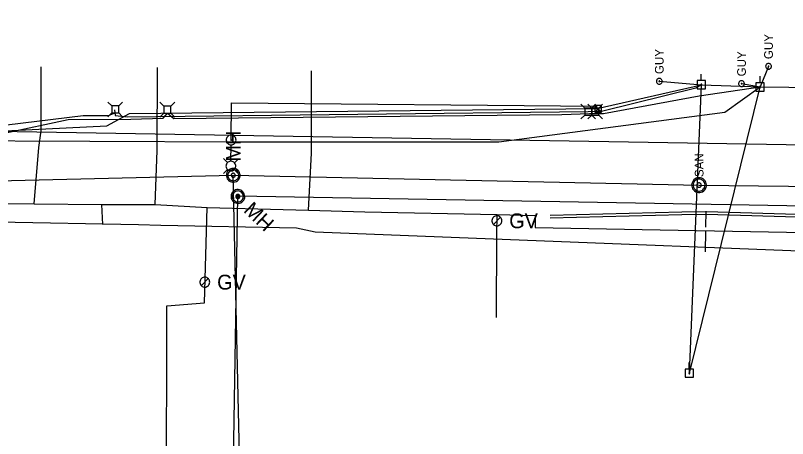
# Model space of a CAD drawing. Extents: x 596028 to 606371, y 330010 to 403088.
# Drawn here: x 603798.7 to 604142, y 337908.1 to 338096 of the extents above; entities that cross this region are included whole.
import ezdxf

# ---------------------------------------------------------------- set-up
doc = ezdxf.new("R2010")
doc.units = 0
for name, color, linetype in [('E_LTG', 7, 'Continuous'), ('E_LTG_CID', 7, 'Continuous'), ('E_UTL_AG_Bold', 7, 'Continuous'), ('E_UTL_E_UG', 7, 'Continuous'), ('E_UTL_EGuyWire', 7, 'Continuous'), ('E_UTL_EPowerPole', 7, 'Continuous'), ('E_UTL_ETransformer', 7, 'Continuous'), ('E_UTL_G', 7, 'Continuous'), ('E_UTL_G_UG', 7, 'Continuous'), ('E_UTL_Overhead', 7, 'Continuous'), ('E_UTL_SAN', 7, 'Continuous'), ('E_UTL_SAN_MH', 7, 'Continuous'), ('E_UTL_SAN_UG', 7, 'Continuous'), ('E_UTL_SAN_UG_MMSD', 7, 'Continuous'), ('E_UTL_T', 7, 'Continuous'), ('E_UTL_T_UG', 7, 'Continuous'), ('E_UTL_TV_UG', 7, 'Continuous')]:
    doc.layers.add(name, color=color, linetype=linetype)

# ---------------------------------------------------------------- blocks, each defined once
blk = doc.blocks.new('ACAD_PROXY_ENTITY_7')
at = {"layer": 'E_UTL_EPowerPole'}
for points in [[(1841391.1, 1030427.5), (1841391.1, 1030436.4)], [(1841396.7, 1030427.5), (1841385.5, 1030427.5)], [(1841385.5, 1030427.5), (1841385.5, 1030416.3)], [(1841391.9, 1030421.9), (1841391.9, 1030422.1), (1841391.9, 1030422.2), (1841391.8, 1030422.3), (1841391.7, 1030422.4), (1841391.6, 1030422.5), (1841391.5, 1030422.6), (1841391.4, 1030422.6), (1841391.2, 1030422.6), (1841391.1, 1030422.6), (1841391, 1030422.6), (1841390.8, 1030422.5), (1841390.7, 1030422.5), (1841390.6, 1030422.4), (1841390.6, 1030422.2), (1841390.5, 1030422.1), (1841390.5, 1030422), (1841390.5, 1030421.8), (1841390.5, 1030421.7), (1841390.6, 1030421.6), (1841390.6, 1030421.5), (1841390.7, 1030421.4), (1841390.8, 1030421.3), (1841391, 1030421.2), (1841391.1, 1030421.2), (1841391.2, 1030421.2), (1841391.4, 1030421.2), (1841391.5, 1030421.3), (1841391.6, 1030421.3), (1841391.7, 1030421.4), (1841391.8, 1030421.5), (1841391.9, 1030421.6), (1841391.9, 1030421.8), (1841391.9, 1030421.9)], [(1841396.7, 1030416.3), (1841396.7, 1030427.5)], [(1841385.5, 1030416.3), (1841396.7, 1030416.3)]]:
    blk.add_lwpolyline(points, dxfattribs=at)
blk = doc.blocks.new('ACAD_PROXY_ENTITY_8')
at = {"layer": 'E_UTL_AG_Bold'}
for points in [[(1843387.7, 1030160.5), (1843382.4, 1030165.8)], [(1843397.2, 1030160.5), (1843387.7, 1030160.5)], [(1843387.7, 1030160.5), (1843387.7, 1030151)], [(1843397.2, 1030160.5), (1843402.5, 1030165.8)], [(1843397.2, 1030151), (1843397.2, 1030160.5)], [(1843387.7, 1030151), (1843382.4, 1030145.7)], [(1843387.7, 1030151), (1843397.2, 1030151)], [(1843397.2, 1030151), (1843402.5, 1030145.7)]]:
    blk.add_lwpolyline(points, dxfattribs=at)
blk = doc.blocks.new('ACAD_PROXY_ENTITY_10')
at = {"layer": 'E_LTG'}
for points in [[(1842242.7, 1034577.4), (1842242.6, 1034578.7), (1842242.2, 1034579.9), (1842241.6, 1034581), (1842240.9, 1034582), (1842239.9, 1034582.9), (1842238.8, 1034583.5), (1842237.6, 1034583.9), (1842236.4, 1034584.1), (1842235.1, 1034584), (1842233.9, 1034583.7), (1842232.7, 1034583.2), (1842231.7, 1034582.5), (1842230.8, 1034581.5), (1842230.2, 1034580.5), (1842229.7, 1034579.3), (1842229.5, 1034578.1), (1842229.5, 1034576.8), (1842229.7, 1034575.6), (1842230.2, 1034574.4), (1842230.8, 1034573.3), (1842231.7, 1034572.4), (1842232.7, 1034571.7), (1842233.9, 1034571.2), (1842235.1, 1034570.9), (1842236.4, 1034570.8), (1842237.6, 1034571), (1842238.8, 1034571.4), (1842239.9, 1034572), (1842240.9, 1034572.9), (1842241.6, 1034573.9), (1842242.2, 1034575), (1842242.6, 1034576.2), (1842242.7, 1034577.4)], [(1842266.8, 1034582.1), (1842261.4, 1034587.5)], [(1842278.1, 1034577.4), (1842277.9, 1034578.7), (1842277.6, 1034579.9), (1842277, 1034581), (1842276.2, 1034582), (1842275.3, 1034582.9), (1842274.2, 1034583.5), (1842273, 1034583.9), (1842271.7, 1034584.1), (1842270.5, 1034584), (1842269.3, 1034583.7), (1842268.1, 1034583.2), (1842267.1, 1034582.5), (1842266.2, 1034581.5), (1842265.5, 1034580.5), (1842265.1, 1034579.3), (1842264.8, 1034578.1), (1842264.8, 1034576.8), (1842265.1, 1034575.6), (1842265.5, 1034574.4), (1842266.2, 1034573.3), (1842267.1, 1034572.4), (1842268.1, 1034571.7), (1842269.3, 1034571.2), (1842270.5, 1034570.9), (1842271.7, 1034570.8), (1842273, 1034571), (1842274.2, 1034571.4), (1842275.3, 1034572), (1842276.2, 1034572.9), (1842277, 1034573.9), (1842277.6, 1034575), (1842277.9, 1034576.2), (1842278.1, 1034577.4)], [(1842276.1, 1034582.1), (1842281.5, 1034587.5)], [(1842236.6, 1034577.4), (1842236.6, 1034577.5), (1842236.5, 1034577.6), (1842236.5, 1034577.7), (1842236.4, 1034577.8), (1842236.4, 1034577.9), (1842236.3, 1034577.9), (1842236.2, 1034577.9), (1842236.1, 1034578), (1842236, 1034578), (1842235.9, 1034577.9), (1842235.8, 1034577.9), (1842235.7, 1034577.8), (1842235.7, 1034577.8), (1842235.6, 1034577.7), (1842235.6, 1034577.6), (1842235.6, 1034577.5), (1842235.6, 1034577.4), (1842235.6, 1034577.3), (1842235.6, 1034577.2), (1842235.7, 1034577.1), (1842235.7, 1034577.1), (1842235.8, 1034577), (1842235.9, 1034577), (1842236, 1034576.9), (1842236.1, 1034576.9), (1842236.2, 1034577), (1842236.3, 1034577), (1842236.4, 1034577), (1842236.4, 1034577.1), (1842236.5, 1034577.2), (1842236.5, 1034577.3), (1842236.6, 1034577.4), (1842236.6, 1034577.4)], [(1842264.7, 1034577.5), (1842242.8, 1034577.5)], [(1842266.8, 1034572.8), (1842261.4, 1034567.4)], [(1842276.1, 1034572.8), (1842281.5, 1034567.4)]]:
    blk.add_lwpolyline(points, dxfattribs=at)
blk = doc.blocks.new('ACAD_PROXY_ENTITY_11')
at = {"layer": 'E_UTL_SAN'}
for points in [[(1841308.5, 1030298.2), (1841306.7, 1030298.1), (1841305, 1030297.6), (1841303.5, 1030296.8), (1841302.1, 1030295.7), (1841300.9, 1030294.3), (1841300, 1030292.8), (1841299.5, 1030291.1), (1841299.2, 1030289.4), (1841299.3, 1030287.6), (1841299.7, 1030285.9), (1841300.4, 1030284.3), (1841301.5, 1030282.8), (1841302.7, 1030281.6), (1841304.2, 1030280.6), (1841305.9, 1030280), (1841307.6, 1030279.7), (1841309.4, 1030279.7), (1841311.1, 1030280), (1841312.8, 1030280.6), (1841314.3, 1030281.6), (1841315.5, 1030282.8), (1841316.6, 1030284.3), (1841317.3, 1030285.9), (1841317.7, 1030287.6), (1841317.8, 1030289.4), (1841317.6, 1030291.1), (1841317, 1030292.8), (1841316.1, 1030294.3), (1841314.9, 1030295.7), (1841313.5, 1030296.8), (1841312, 1030297.6), (1841310.3, 1030298.1), (1841308.5, 1030298.2)], [(1841308.5, 1030296.4), (1841307.1, 1030296.2), (1841305.7, 1030295.8), (1841304.5, 1030295.2), (1841303.4, 1030294.3), (1841302.4, 1030293.2), (1841301.7, 1030292), (1841301.3, 1030290.7), (1841301.1, 1030289.3), (1841301.1, 1030287.9), (1841301.5, 1030286.5), (1841302.1, 1030285.2), (1841302.9, 1030284), (1841303.9, 1030283.1), (1841305.1, 1030282.3), (1841306.4, 1030281.8), (1841307.8, 1030281.5), (1841309.2, 1030281.5), (1841310.6, 1030281.8), (1841311.9, 1030282.3), (1841313.1, 1030283.1), (1841314.1, 1030284), (1841315, 1030285.2), (1841315.5, 1030286.5), (1841315.9, 1030287.9), (1841315.9, 1030289.3), (1841315.7, 1030290.7), (1841315.3, 1030292), (1841314.6, 1030293.2), (1841313.6, 1030294.3), (1841312.5, 1030295.2), (1841311.3, 1030295.8), (1841309.9, 1030296.2), (1841308.5, 1030296.4)], [(1841308.5, 1030291.7), (1841308, 1030291.7), (1841307.5, 1030291.5), (1841307, 1030291.3), (1841306.6, 1030290.9), (1841306.2, 1030290.5), (1841306, 1030290.1), (1841305.8, 1030289.6), (1841305.7, 1030289.1), (1841305.7, 1030288.5), (1841305.9, 1030288), (1841306.1, 1030287.5), (1841306.4, 1030287.1), (1841306.8, 1030286.7), (1841307.2, 1030286.4), (1841307.7, 1030286.2), (1841308.2, 1030286.1), (1841308.8, 1030286.1), (1841309.3, 1030286.2), (1841309.8, 1030286.4), (1841310.2, 1030286.7), (1841310.6, 1030287.1), (1841310.9, 1030287.5), (1841311.1, 1030288), (1841311.3, 1030288.5), (1841311.3, 1030289.1), (1841311.2, 1030289.6), (1841311, 1030290.1), (1841310.8, 1030290.5), (1841310.4, 1030290.9), (1841310, 1030291.3), (1841309.5, 1030291.5), (1841309, 1030291.7), (1841308.5, 1030291.7)]]:
    blk.add_lwpolyline(points, dxfattribs=at)
blk.add_text('MH', height=20.12, rotation=90, dxfattribs=at).set_placement((1841318.6, 1030307.5))
blk = doc.blocks.new('ACAD_PROXY_ENTITY_19')
at = {"layer": 'E_UTL_G'}
for points in [[(1843225.4, 1030136.5), (1843225.2, 1030137.7), (1843224.9, 1030139), (1843224.3, 1030140.1), (1843223.5, 1030141.1), (1843222.5, 1030141.9), (1843221.4, 1030142.6), (1843220.2, 1030143), (1843219, 1030143.2), (1843217.7, 1030143.1), (1843216.5, 1030142.8), (1843215.3, 1030142.3), (1843214.3, 1030141.5), (1843213.4, 1030140.6), (1843212.7, 1030139.5), (1843212.2, 1030138.4), (1843212, 1030137.1), (1843212, 1030135.8), (1843212.2, 1030134.6), (1843212.7, 1030133.4), (1843213.4, 1030132.3), (1843214.3, 1030131.4), (1843215.3, 1030130.7), (1843216.5, 1030130.1), (1843217.7, 1030129.8), (1843219, 1030129.8), (1843220.2, 1030129.9), (1843221.4, 1030130.4), (1843222.5, 1030131), (1843223.5, 1030131.8), (1843224.3, 1030132.8), (1843224.9, 1030134), (1843225.2, 1030135.2), (1843225.4, 1030136.5)], [(1843213.9, 1030131.7), (1843223.4, 1030141.2)]]:
    blk.add_lwpolyline(points, dxfattribs=at)
blk.add_text('GV', height=20.12, dxfattribs=at).set_placement((1843235.4, 1030126.4))

msp = doc.modelspace()

# ---------------------------------------------------------------- linework, layer by layer
at = {"layer": 'E_LTG_CID'}
msp.add_lwpolyline([(603894.62, 338040.7), (603894.72, 338057.11), (604057.25, 338055.68)], dxfattribs=at)
at = {"layer": 'E_UTL_E_UG'}
msp.add_line((604057.26, 338054.68), (604103.64, 338065.21), dxfattribs=at)
for points in [[(603839.32, 338046.99), (603849.47, 338052.42), (604057.26, 338054.68)], [(603604.81, 338053.24), (603627.15, 338051.8), (603659.4, 338049.36), (603720.29, 338046.02), (603787.9, 338044.47), (603839.32, 338046.99)]]:
    msp.add_lwpolyline(points, dxfattribs=at)
at = {"layer": 'E_UTL_EGuyWire'}
for p, q in [((604133.5, 338073.37), (604129.76, 338064.26)), ((604084.95, 338066.74), (604103.64, 338065.21)), ((604121.49, 338065.7), (604129.76, 338064.26))]:
    msp.add_line(p, q, dxfattribs=at)
for points in [[(604133.5, 338074.66), (604133.26, 338074.63), (604133.02, 338074.56), (604132.81, 338074.45), (604132.61, 338074.3), (604132.45, 338074.12), (604132.33, 338073.91), (604132.25, 338073.67), (604132.22, 338073.43), (604132.23, 338073.19), (604132.29, 338072.95), (604132.39, 338072.73), (604132.53, 338072.53), (604132.71, 338072.36), (604132.91, 338072.23), (604133.14, 338072.14), (604133.38, 338072.09), (604133.62, 338072.09), (604133.86, 338072.14), (604134.09, 338072.23), (604134.29, 338072.36), (604134.47, 338072.53), (604134.61, 338072.73), (604134.71, 338072.95), (604134.77, 338073.19), (604134.78, 338073.43), (604134.75, 338073.67), (604134.67, 338073.91), (604134.54, 338074.12), (604134.38, 338074.3), (604134.19, 338074.45), (604133.98, 338074.56), (604133.74, 338074.63), (604133.5, 338074.66)], [(604133.5, 338073.53), (604133.47, 338073.53), (604133.44, 338073.52), (604133.41, 338073.51), (604133.39, 338073.49), (604133.37, 338073.47), (604133.35, 338073.44), (604133.34, 338073.41), (604133.34, 338073.38), (604133.34, 338073.35), (604133.35, 338073.32), (604133.36, 338073.29), (604133.38, 338073.27), (604133.4, 338073.25), (604133.43, 338073.23), (604133.45, 338073.22), (604133.48, 338073.21), (604133.51, 338073.21), (604133.54, 338073.22), (604133.57, 338073.23), (604133.6, 338073.25), (604133.62, 338073.27), (604133.64, 338073.29), (604133.65, 338073.32), (604133.66, 338073.35), (604133.66, 338073.38), (604133.65, 338073.41), (604133.64, 338073.44), (604133.63, 338073.47), (604133.61, 338073.49), (604133.59, 338073.51), (604133.56, 338073.52), (604133.53, 338073.53), (604133.5, 338073.53)], [(604084.95, 338068.02), (604084.71, 338068), (604084.47, 338067.93), (604084.25, 338067.82), (604084.06, 338067.66), (604083.9, 338067.48), (604083.78, 338067.27), (604083.7, 338067.04), (604083.67, 338066.8), (604083.68, 338066.55), (604083.74, 338066.32), (604083.84, 338066.09), (604083.98, 338065.9), (604084.15, 338065.73), (604084.36, 338065.6), (604084.59, 338065.5), (604084.83, 338065.46), (604085.07, 338065.46), (604085.31, 338065.5), (604085.54, 338065.6), (604085.74, 338065.73), (604085.92, 338065.9), (604086.06, 338066.09), (604086.16, 338066.32), (604086.22, 338066.55), (604086.23, 338066.8), (604086.2, 338067.04), (604086.12, 338067.27), (604085.99, 338067.48), (604085.83, 338067.66), (604085.64, 338067.82), (604085.42, 338067.93), (604085.19, 338068), (604084.95, 338068.02)], [(604084.95, 338066.9), (604084.92, 338066.89), (604084.89, 338066.88), (604084.86, 338066.87), (604084.84, 338066.85), (604084.82, 338066.83), (604084.8, 338066.8), (604084.79, 338066.77), (604084.79, 338066.74), (604084.79, 338066.71), (604084.8, 338066.68), (604084.81, 338066.66), (604084.83, 338066.63), (604084.85, 338066.61), (604084.87, 338066.59), (604084.9, 338066.58), (604084.93, 338066.58), (604084.96, 338066.58), (604084.99, 338066.58), (604085.02, 338066.59), (604085.05, 338066.61), (604085.07, 338066.63), (604085.09, 338066.66), (604085.1, 338066.68), (604085.11, 338066.71), (604085.11, 338066.74), (604085.1, 338066.77), (604085.09, 338066.8), (604085.08, 338066.83), (604085.06, 338066.85), (604085.03, 338066.87), (604085.01, 338066.88), (604084.98, 338066.89), (604084.95, 338066.9)], [(604121.49, 338066.98), (604121.25, 338066.96), (604121.02, 338066.89), (604120.8, 338066.78), (604120.61, 338066.63), (604120.45, 338066.44), (604120.33, 338066.23), (604120.25, 338066), (604120.21, 338065.76), (604120.22, 338065.51), (604120.28, 338065.28), (604120.38, 338065.06), (604120.53, 338064.86), (604120.7, 338064.69), (604120.91, 338064.56), (604121.13, 338064.47), (604121.37, 338064.42), (604121.62, 338064.42), (604121.86, 338064.47), (604122.08, 338064.56), (604122.29, 338064.69), (604122.46, 338064.86), (604122.61, 338065.06), (604122.71, 338065.28), (604122.77, 338065.51), (604122.78, 338065.76), (604122.74, 338066), (604122.66, 338066.23), (604122.54, 338066.44), (604122.38, 338066.63), (604122.19, 338066.78), (604121.97, 338066.89), (604121.74, 338066.96), (604121.49, 338066.98)], [(604121.49, 338065.86), (604121.46, 338065.85), (604121.44, 338065.85), (604121.41, 338065.83), (604121.38, 338065.81), (604121.36, 338065.79), (604121.35, 338065.76), (604121.34, 338065.73), (604121.33, 338065.7), (604121.34, 338065.67), (604121.34, 338065.64), (604121.36, 338065.62), (604121.37, 338065.59), (604121.4, 338065.57), (604121.42, 338065.55), (604121.45, 338065.54), (604121.48, 338065.54), (604121.51, 338065.54), (604121.54, 338065.54), (604121.57, 338065.55), (604121.59, 338065.57), (604121.62, 338065.59), (604121.63, 338065.62), (604121.65, 338065.64), (604121.65, 338065.67), (604121.66, 338065.7), (604121.65, 338065.73), (604121.64, 338065.76), (604121.63, 338065.79), (604121.61, 338065.81), (604121.58, 338065.83), (604121.55, 338065.85), (604121.53, 338065.85), (604121.49, 338065.86)]]:
    msp.add_lwpolyline(points, dxfattribs=at)
at = {"layer": 'E_UTL_EPowerPole'}
for points in [[(604103.61, 338067.05), (604103.61, 338069.96)], [(604129.73, 338066.1), (604129.73, 338069.01)], [(604105.46, 338067.05), (604101.77, 338067.05)], [(604101.77, 338067.05), (604101.77, 338063.36)], [(604103.88, 338065.21), (604103.88, 338065.25), (604103.87, 338065.3), (604103.84, 338065.34), (604103.82, 338065.37), (604103.78, 338065.4), (604103.74, 338065.42), (604103.7, 338065.44), (604103.66, 338065.45), (604103.61, 338065.44), (604103.57, 338065.43), (604103.52, 338065.41), (604103.49, 338065.39), (604103.46, 338065.36), (604103.43, 338065.32), (604103.42, 338065.28), (604103.41, 338065.23), (604103.41, 338065.19), (604103.42, 338065.14), (604103.43, 338065.1), (604103.46, 338065.06), (604103.49, 338065.03), (604103.52, 338065), (604103.57, 338064.98), (604103.61, 338064.97), (604103.66, 338064.97), (604103.7, 338064.98), (604103.74, 338064.99), (604103.78, 338065.01), (604103.82, 338065.04), (604103.84, 338065.08), (604103.87, 338065.12), (604103.88, 338065.16), (604103.88, 338065.21)], [(604105.46, 338063.36), (604105.46, 338067.05)], [(604131.58, 338066.1), (604127.89, 338066.1)], [(604127.89, 338066.1), (604127.89, 338062.41)], [(604130, 338064.26), (604130, 338064.3), (604129.98, 338064.34), (604129.96, 338064.38), (604129.94, 338064.42), (604129.9, 338064.45), (604129.86, 338064.47), (604129.82, 338064.49), (604129.77, 338064.49), (604129.73, 338064.49), (604129.69, 338064.48), (604129.64, 338064.46), (604129.61, 338064.44), (604129.58, 338064.4), (604129.55, 338064.37), (604129.53, 338064.32), (604129.53, 338064.28), (604129.53, 338064.23), (604129.53, 338064.19), (604129.55, 338064.15), (604129.58, 338064.11), (604129.61, 338064.08), (604129.64, 338064.05), (604129.69, 338064.03), (604129.73, 338064.02), (604129.77, 338064.02), (604129.82, 338064.02), (604129.86, 338064.04), (604129.9, 338064.06), (604129.94, 338064.09), (604129.96, 338064.13), (604129.98, 338064.17), (604130, 338064.21), (604130, 338064.26)], [(604131.58, 338062.41), (604131.58, 338066.1)], [(604101.77, 338063.36), (604105.46, 338063.36)], [(604127.89, 338062.41), (604131.58, 338062.41)]]:
    msp.add_lwpolyline(points, dxfattribs=at)
at = {"layer": 'E_UTL_ETransformer'}
for p, q in [((604056.27, 338055.97), (604059.27, 338052.97)), ((604059.27, 338055.97), (604056.27, 338052.97))]:
    msp.add_line(p, q, dxfattribs=at)
msp.add_lwpolyline([(604056.27, 338052.97), (604059.27, 338052.97), (604059.27, 338055.97), (604056.27, 338055.97)], close=True, dxfattribs=at)
at = {"layer": 'E_UTL_G_UG'}
for p, q in [((603810.15, 338044.77), (603810.24, 338073.2)), ((603861.78, 338036.07), (603861.9, 338072.88)), ((603930.29, 338049.48), (603930.36, 338071.45)), ((603860.91, 338012.03), (603861.78, 338036.07)), ((603837.54, 338003.08), (603837.16, 338012.04)), ((604012.66, 337998.63), (604012.83, 338007.59)), ((604012.54, 337961.83), (604012.66, 337998.63))]:
    msp.add_line(p, q, dxfattribs=at)
for points in [[(603929, 338009.55), (603930.35, 338034.75), (603930.29, 338049.48)], [(603807.06, 338012.31), (603809.14, 338037.28), (603810.15, 338044.77)], [(604036.38, 338007.29), (604094.93, 338008.7), (604105.86, 338008.92), (604151.14, 338007.64), (604192.37, 338006.27), (604238.01, 338005.01), (604257.33, 338004.4), (604292.99, 338030.64), (604323.62, 338029.78)], [(604036.41, 338006.09), (604094.96, 338007.5), (604105.86, 338007.72), (604151.1, 338006.44), (604192.34, 338005.07), (604237.98, 338003.81), (604257.71, 338003.19), (604293.37, 338029.43), (604323.59, 338028.58)], [(603659.13, 338014.92), (603660.24, 338014.99), (603710.2, 338013.48), (603807.06, 338012.31), (603837.16, 338012.04), (603860.91, 338012.03), (603883.92, 338010.64)], [(603857.61, 337826.63), (603865.95, 337876.92), (603866.02, 337966.94), (603882.73, 337968.38), (603883.92, 338010.64)], [(603883.92, 338010.64), (603929, 338009.55), (603954.09, 338008.77), (604012.83, 338007.59), (604029.73, 338007.09)], [(604105.59, 338008.98), (604105.5, 338002)], [(604029.73, 338007.09), (604029.74, 338001.83), (604085.34, 338000.71), (604165.59, 337999.27), (604217.37, 337998.29), (604240.59, 337996.82), (604279.37, 337995.16), (604329.48, 337991.52)], [(604105.48, 338000.35), (604105.35, 337991.05)]]:
    msp.add_lwpolyline(points, dxfattribs=at)
at = {"layer": 'E_UTL_Overhead'}
msp.add_line((604098.33, 337937.1), (604103.64, 338065.21), dxfattribs=at)
for points in [[(604103.64, 338065.21), (604129.71, 338064.26), (604269.62, 338062.62), (604344.53, 338119.28), (604560.83, 338082.73), (604641.4, 338068.29), (604696.28, 338059.45), (604715.56, 338054.88), (604786.57, 338054.03), (604829.08, 338053.72), (604872.92, 338052.19), (604977.47, 338050.01), (605123.72, 338048.42), (605215.39, 338038.9)], [(604098.33, 337937.1), (604129.71, 338064.26)]]:
    msp.add_lwpolyline(points, dxfattribs=at)
at = {"layer": 'E_UTL_SAN_MH'}
for points in [[(604102.63, 338023.93), (604102.01, 338023.87), (604101.4, 338023.69), (604100.85, 338023.4), (604100.35, 338023.01), (604099.94, 338022.54), (604099.63, 338022), (604099.42, 338021.4), (604099.33, 338020.78), (604099.36, 338020.16), (604099.51, 338019.55), (604099.77, 338018.98), (604100.14, 338018.46), (604100.59, 338018.03), (604101.12, 338017.69), (604101.7, 338017.46), (604102.32, 338017.34), (604102.94, 338017.34), (604103.56, 338017.46), (604104.14, 338017.69), (604104.67, 338018.03), (604105.12, 338018.46), (604105.49, 338018.98), (604105.75, 338019.55), (604105.9, 338020.16), (604105.93, 338020.78), (604105.84, 338021.4), (604105.63, 338022), (604105.32, 338022.54), (604104.91, 338023.01), (604104.41, 338023.4), (604103.86, 338023.69), (604103.26, 338023.87), (604102.63, 338023.93)], [(604102.63, 338023.27), (604102.13, 338023.22), (604101.65, 338023.08), (604101.2, 338022.85), (604100.81, 338022.54), (604100.48, 338022.16), (604100.23, 338021.72), (604100.07, 338021.25), (604099.99, 338020.75), (604100.02, 338020.25), (604100.14, 338019.76), (604100.34, 338019.31), (604100.64, 338018.9), (604101, 338018.55), (604101.42, 338018.28), (604101.89, 338018.09), (604102.38, 338018), (604102.88, 338018), (604103.37, 338018.09), (604103.84, 338018.28), (604104.26, 338018.55), (604104.63, 338018.9), (604104.92, 338019.31), (604105.13, 338019.76), (604105.24, 338020.25), (604105.27, 338020.75), (604105.2, 338021.25), (604105.03, 338021.72), (604104.78, 338022.16), (604104.45, 338022.54), (604104.06, 338022.85), (604103.61, 338023.08), (604103.13, 338023.22), (604102.63, 338023.27)], [(604102.63, 338021.62), (604102.44, 338021.6), (604102.26, 338021.54), (604102.1, 338021.46), (604101.95, 338021.34), (604101.82, 338021.2), (604101.73, 338021.04), (604101.67, 338020.86), (604101.64, 338020.67), (604101.65, 338020.48), (604101.7, 338020.3), (604101.77, 338020.13), (604101.88, 338019.98), (604102.02, 338019.85), (604102.18, 338019.75), (604102.35, 338019.68), (604102.54, 338019.64), (604102.72, 338019.64), (604102.91, 338019.68), (604103.08, 338019.75), (604103.24, 338019.85), (604103.38, 338019.98), (604103.49, 338020.13), (604103.57, 338020.3), (604103.61, 338020.48), (604103.62, 338020.67), (604103.59, 338020.86), (604103.53, 338021.04), (604103.44, 338021.2), (604103.31, 338021.34), (604103.17, 338021.46), (604103, 338021.54), (604102.82, 338021.6), (604102.63, 338021.62)]]:
    msp.add_lwpolyline(points, dxfattribs=at)
msp.add_circle((603897.65, 338015.63), 0.45, dxfattribs=at)
at = {"layer": 'E_UTL_SAN_UG'}
for p in [(603701.92, 338020.41), (603898.31, 337900.75)]:
    msp.add_line(p, (603895.55, 338024.99), dxfattribs=at)
for points in [[(603895.55, 338024.99), (604102.65, 338020.61)], [(604102.65, 338020.61), (604287.7, 338018.55)]]:
    msp.add_lwpolyline(points, dxfattribs=at)
at = {"layer": 'E_UTL_SAN_UG_MMSD'}
for p, q in [((603141.66, 338055.73), (604202.07, 338037.6)), ((603897.65, 338015.8), (604665.17, 338002.68))]:
    msp.add_line(p, q, dxfattribs=at)
msp.add_lwpolyline([(603886.8, 337355.91), (603897.65, 338015.63)], dxfattribs=at)
at = {"layer": 'E_UTL_T_UG'}
msp.add_line((603599.45, 338007.74), (603853.39, 338003.2), dxfattribs=at)
for points in [[(604053.34, 338053.31), (604059.81, 338053.6), (604101.13, 338063.8), (604103.64, 338065.21)], [(603842.76, 338054.1), (603843.06, 338051.58), (603848.49, 338050.96)], [(603669, 338051.76), (603672.99, 338049.45), (603720.35, 338047.39), (603787.56, 338046.44), (603828.77, 338051.55)], [(603828.77, 338051.55), (603840.09, 338051.61), (603843.08, 338052.7)], [(603848.5, 338050.97), (604053.34, 338053.31)], [(603853.39, 338003.2), (603863.38, 338002.89), (603923.6, 338001.66), (603932.04, 337999.82)], [(603932.04, 337999.82), (604249.26, 337987.48), (604268.59, 337974.93)]]:
    msp.add_lwpolyline(points, dxfattribs=at)
at = {"layer": 'E_UTL_TV_UG'}
for points in [[(603602.69, 338042.21), (603664.91, 338041.66), (603765.11, 338040.43), (603898.32, 338039.89), (604013.63, 338039.78), (604114.06, 338053.03), (604129.71, 338064.26)], [(603604.27, 338051.06), (603665.39, 338048.69), (603667.58, 338052.08), (603673.87, 338048.32), (603727.54, 338041.72), (603760.53, 338043.44), (603794.48, 338043.87), (603822.16, 338049.71), (603850.03, 338049.88), (603864.37, 338050.37), (603866.29, 338052.56), (603869.2, 338050.26), (604041.63, 338052.04), (604053.93, 338052.46), (604060.19, 338052.43), (604102.72, 338060.26), (604129.71, 338064.26)]]:
    msp.add_lwpolyline(points, dxfattribs=at)

# ---------------------------------------------------------------- block references
at = {"layer": 'E_LTG', "xscale": 0.32808333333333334, "yscale": 0.32808333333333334, "rotation": -90.56997623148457}
msp.add_blockref('ACAD_PROXY_ENTITY_10', (270496.32, 945794.27), dxfattribs=at)
at = {"layer": 'E_UTL_EPowerPole', "xscale": 0.32808333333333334, "yscale": 0.32808333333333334}
msp.add_blockref('ACAD_PROXY_ENTITY_7', (-31.44, -127.15), dxfattribs=at)
at = {"layer": 'E_UTL_G', "xscale": 0.32808333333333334, "yscale": 0.32808333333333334}
for p in [(-716.59, 34.16), (-846.42, 6.92)]:
    msp.add_blockref('ACAD_PROXY_ENTITY_19', p, dxfattribs=at)
at = {"layer": 'E_UTL_SAN_MH', "xscale": 0.32808333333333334, "yscale": 0.32808333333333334}
msp.add_blockref('ACAD_PROXY_ENTITY_11', (-207.07, 4.36), dxfattribs=at)
at = {"layer": 'E_UTL_SAN_MH', "xscale": 0.32808333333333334, "yscale": 0.3280833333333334, "rotation": -133.43362069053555}
msp.add_blockref('ACAD_PROXY_ENTITY_11', (773765.59, 1009091.44), dxfattribs=at)
at = {"layer": 'E_UTL_T', "xscale": 0.32808333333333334, "yscale": 0.32808333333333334}
for p in [(-943.26, 77.31), (-920.05, 77.17), (-732.99, 76.37), (-729.89, 76.37)]:
    msp.add_blockref('ACAD_PROXY_ENTITY_8', p, dxfattribs=at)

# ---------------------------------------------------------------- texts
at = {"layer": 'E_UTL_EGuyWire'}
for p in [(604135.42, 338076.58), (604086.87, 338069.94), (604123.42, 338068.91)]:
    msp.add_text('GUY', height=3.85, rotation=90, dxfattribs=at).set_placement(p)
at = {"layer": 'E_UTL_SAN_MH'}
msp.add_text('SAN', height=3.849, rotation=90, dxfattribs=at).set_placement((604104.58, 338024.19))

doc.saveas('drawing.dxf')
